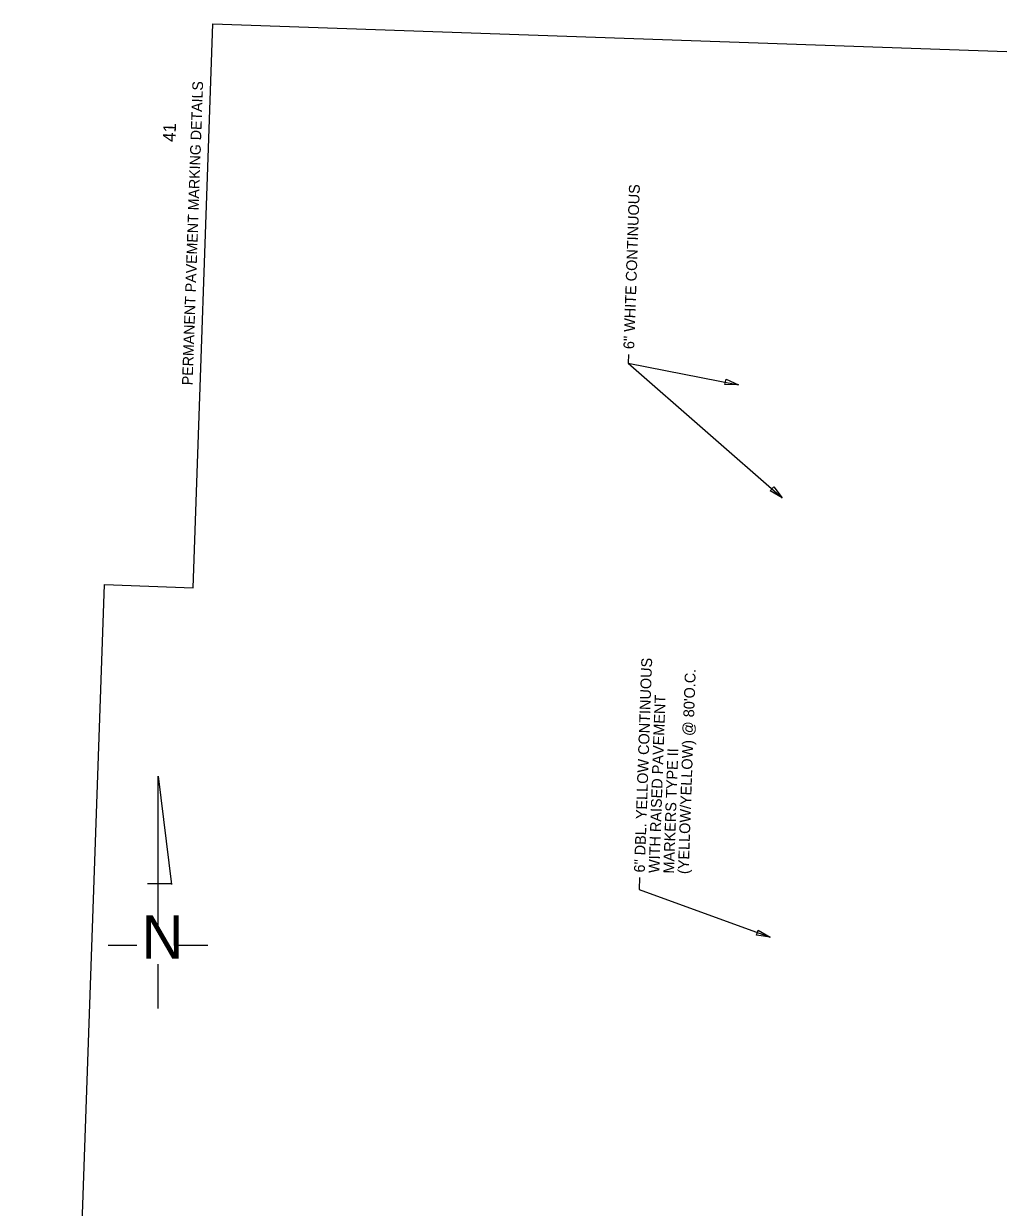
# Model space of a CAD drawing. Extents: x 633912 to 634995, y 289794 to 291427.
# Drawn here: x 633912 to 634453, y 290770 to 291427 of the extents above; entities that cross this region are included whole.
import ezdxf

# ---------------------------------------------------------------- set-up
doc = ezdxf.new("R2010")
doc.units = 0
for name, color, linetype in [('Level 24', 7, 'Continuous'), ('Level 63', 7, 'Continuous'), ('R_Border', 7, 'Continuous'), ('R_Border Notes', 7, 'Continuous'), ('R_Draft', 7, 'Continuous'), ('ROAD', 7, 'Continuous')]:
    doc.layers.add(name, color=color, linetype=linetype)

msp = doc.modelspace()

# ---------------------------------------------------------------- linework, layer by layer
at = {"layer": 'Level 24'}
for points in [[(634302.2, 291230.09), (634309.18, 291226.95), (634301.53, 291227.16)], [(634328.74, 291170.33), (634333.45, 291164.3), (634326.78, 291168.05)], [(634320.05, 290924.27), (634326.68, 290920.45), (634319.1, 290921.43)]]:
    msp.add_lwpolyline(points, close=True, dxfattribs=at)
at = {"layer": 'Level 63'}
msp.add_lwpolyline([(634938.65, 289793.65), (633912.26, 289829.49), (633957.19, 291116.06), (634006.28, 291114.34), (634017.21, 291427.35), (634994.51, 291393.22)], close=True, dxfattribs=at)
at = {"layer": 'R_Draft'}
for p, q in [((633986.85, 291009.72), (633994.36, 290949.71)), ((633986.85, 290925.81), (633986.85, 291009.72)), ((633981.02, 290950.15), (633994.36, 290950.15)), ((633959.25, 290915.92), (633975.16, 290915.92)), ((633997.44, 290915.92), (634014.44, 290915.92)), ((633986.85, 290880.8), (633986.85, 290905.47))]:
    msp.add_line(p, q, dxfattribs=at)
at = {"layer": 'ROAD'}
for p, q in [((634248.07, 291243.81), (634247.9, 291238.96)), ((634247.9, 291238.96), (634309.18, 291226.95)), ((634247.9, 291238.96), (634333.45, 291164.3)), ((634254.13, 290953.43), (634253.9, 290946.79)), ((634253.9, 290946.79), (634326.68, 290920.45))]:
    msp.add_line(p, q, dxfattribs=at)

# ---------------------------------------------------------------- texts
at = {"layer": 'R_Border'}
msp.add_text('41', height=7, rotation=88, dxfattribs=at).set_placement((633996.51, 291361.66))
at = {"layer": 'R_Border Notes'}
msp.add_text('PERMANENT PAVEMENT MARKING DETAILS', height=5.8876, rotation=88, dxfattribs=at).set_placement((634006.01, 291226.61))
at = {"layer": 'R_Draft'}
msp.add_text('N', height=24, rotation=360, dxfattribs=at).set_placement((633977.75, 290908.53))
at = {"layer": 'ROAD'}
for s, p in [('6" WHITE CONTINUOUS', (634251.2, 291246.66)), ('6" DBL. YELLOW CONTINUOUS', (634257.07, 290956.18)), ("(YELLOW/YELLOW) @ 80'O.C.", (634281.43, 290955.33)), ('WITH RAISED PAVEMENT', (634265.19, 290955.9)), ('MARKERS TYPE II', (634273.31, 290955.61))]:
    msp.add_text(s, height=6, rotation=87.99999, dxfattribs=at).set_placement(p)

doc.saveas('drawing.dxf')
